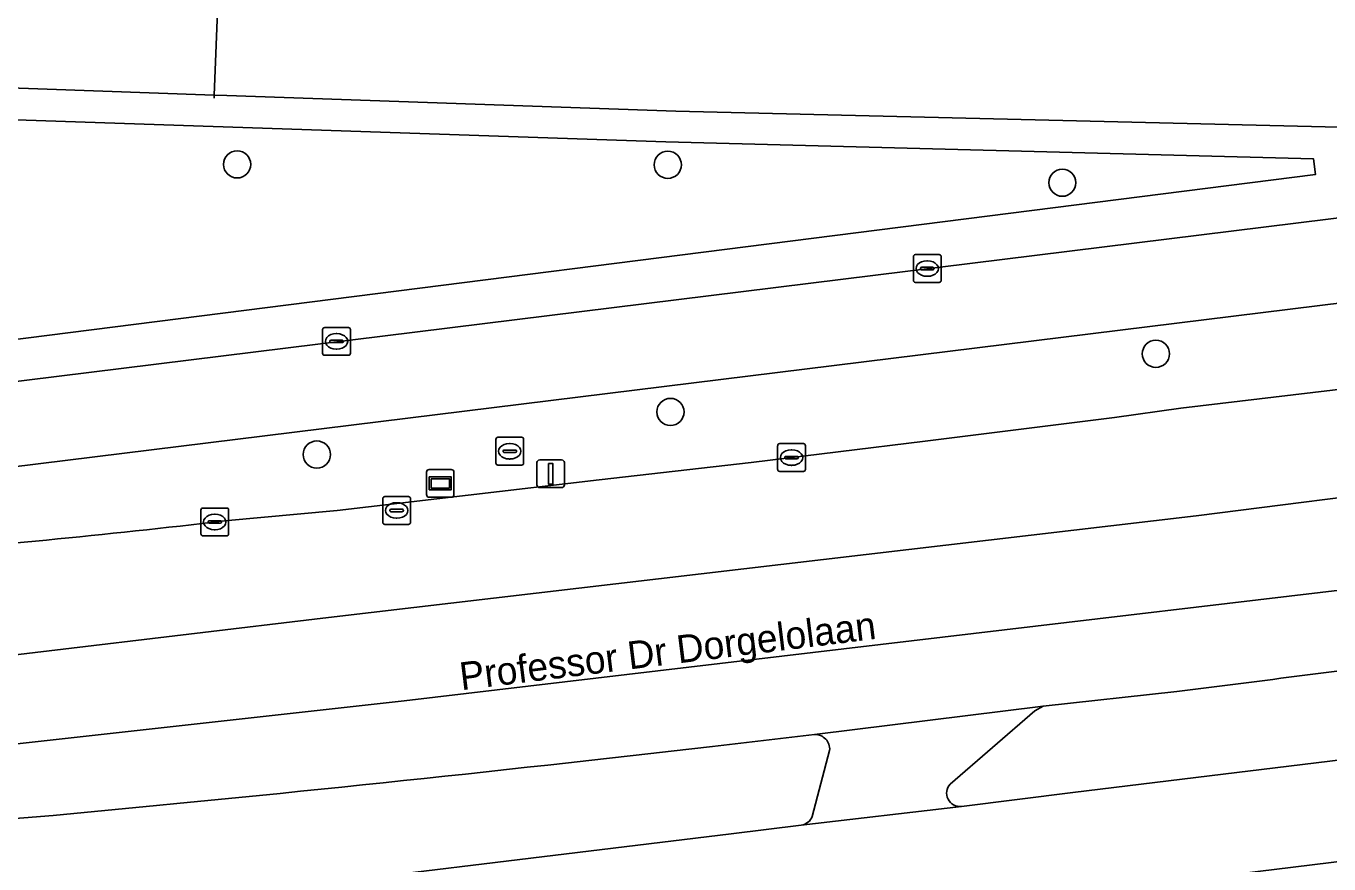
# Model space of a CAD drawing. Extents: x 161477 to 163040, y 383680 to 384871.
# Drawn here: x 161710.95 to 161757.86, y 384006.51 to 384036.66 of the extents above; entities that cross this region are included whole.
import ezdxf

# ---------------------------------------------------------------- set-up
doc = ezdxf.new("R2010")
doc.units = 0
for name, color, linetype in [('IMGEO_Berm_groen', 7, 'Continuous'), ('IMGEO_Boom', 7, 'Continuous'), ('IMGEO_Fietspad_gesloten', 7, 'Continuous'), ('IMGEO_Fietspad_open', 7, 'Continuous'), ('IMGEO_Kolk', 7, 'Continuous'), ('IMGEO_Lichtmast', 7, 'Continuous'), ('IMGEO_Lijnafwatering', 7, 'Continuous'), ('IMGEO_Openbare_ruimte_label', 7, 'Continuous'), ('IMGEO_Rijbaan_lokaal_gesloten', 7, 'Continuous'), ('IMGEO_Rioolput', 7, 'Continuous'), ('IMGEO_Verklikker', 7, 'Continuous'), ('IMGEO_Voetpad_gesloten', 7, 'Continuous'), ('IMGEO_Voetpad_open', 7, 'Continuous')]:
    doc.layers.add(name, color=color, linetype=linetype)

msp = doc.modelspace()

# ---------------------------------------------------------------- linework, layer by layer
at = {"layer": 'IMGEO_Berm_groen'}
for points in [[(161718.096, 384018.853), (161722.153, 384019.231), (161731.582, 384020.326), (161737.062, 384020.952), (161743.325, 384021.716), (161750.139, 384022.575), (161752.521, 384022.902), (161758.694, 384023.638), (161765.407, 384024.434), (161773.852, 384025.569), (161780.934, 384026.394), (161789.811, 384027.457), (161796.662, 384028.308), (161802.176, 384029.078), (161803.723, 384029.183), (161808.93, 384029.766), (161813.278, 384030.282), (161823.202, 384031.479), (161830.293, 384032.344), (161838.36, 384033.362), (161846.778, 384034.306), (161857.408, 384035.62), (161864.1, 384036.367)], [(161757.379, 384031.316), (161757.305, 384031.876), (161733.987, 384032.488), (161701.381, 384033.589), (161700.35, 384033.55), (161699.371, 384033.385)], [(161693.867, 384029.204), (161693.407, 384028.292), (161693.069, 384027.332), (161692.822, 384026.215), (161693.842, 384025.924), (161693.834, 384026.258), (161702.945, 384026.672), (161702.989, 384026.278), (161703.08, 384024.434), (161757.379, 384031.316)], [(161763.653, 384027.361), (161706.222, 384020.27), (161703.259, 384019.694)], [(161744.626, 384008.574), (161748.637, 384009.081), (161823.343, 384018.177), (161854.166, 384022.062), (161862.148, 384023.025)], [(161752.379, 384012.714), (161747.565, 384012.187), (161747.265, 384012.019), (161744.223, 384009.381)], [(161739.341, 384011.163), (161735.662, 384010.732)], [(161739.256, 384008.22), (161739.881, 384010.593)], [(161711.93, 384008.251), (161698.187, 384007.159), (161695.907, 384007), (161695.634, 384006.981), (161696.191, 384002.723), (161696.412, 384002.75), (161736.335, 384007.586), (161738.86, 384007.907)]]:
    msp.add_lwpolyline(points, dxfattribs=at)
for centre, radius, start, end in [((161683.186, 384312.146), 295.363, 274.28671, 276.78778), ((161586.568, 385343.237), 1340.815, 277.10362, 277.501004), ((161739.357, 384010.638), 0.526, 355.1239, 91.7798), ((161606.132, 385135.008), 1131.713, 275.364128, 276.572189), ((161744.576, 384009.053), 0.482, 137.1227, 275.9506), ((161738.801, 384008.388), 0.485, 276.9717, 339.6743)]:
    msp.add_arc(centre, radius, start, end, dxfattribs=at)
at = {"layer": 'IMGEO_Boom'}
for centre in [(161718.548, 384031.679), (161734.053, 384031.665), (161748.259, 384031.02), (161751.627, 384024.864), (161734.149, 384022.771), (161721.419, 384021.238)]:
    msp.add_circle(centre, 0.489, dxfattribs=at)
at = {"layer": 'IMGEO_Fietspad_gesloten'}
msp.add_lwpolyline([(161700.668, 384034.787), (161717.726, 384034.171), (161718.177, 384034.155), (161734.34, 384033.599), (161758.72, 384033.003), (161764.181, 384032.902)], dxfattribs=at)
at = {"layer": 'IMGEO_Fietspad_open'}
for points in [[(161763.653, 384027.361), (161763.253, 384030.692), (161762.659, 384030.32), (161759.087, 384029.863), (161705.045, 384023.188), (161702.143, 384022.584), (161699.157, 384022.191), (161694.128, 384021.966), (161693.678, 384021.946), (161694.02, 384019.337), (161694.073, 384018.934), (161694.486, 384018.953), (161695.454, 384018.996), (161699.282, 384019.167)], [(161703.259, 384019.694), (161706.222, 384020.27), (161763.653, 384027.361)]]:
    msp.add_lwpolyline(points, dxfattribs=at)
at = {"layer": 'IMGEO_Kolk'}
for p, q in [((161742.896, 384027.506), (161742.896, 384028.358)), ((161742.971, 384028.432), (161743.823, 384028.432)), ((161743.384, 384028.212), (161743.409, 384028.212)), ((161743.897, 384028.358), (161743.897, 384027.506)), ((161743.155, 384027.926), (161743.155, 384027.938)), ((161743.593, 384027.889), (161743.195, 384027.889)), ((161743.198, 384027.975), (161743.596, 384027.975)), ((161743.407, 384027.652), (161743.382, 384027.652)), ((161743.639, 384027.938), (161743.639, 384027.926)), ((161743.823, 384027.432), (161742.971, 384027.432)), ((161721.628, 384024.883), (161721.628, 384025.735)), ((161721.703, 384025.809), (161722.555, 384025.809)), ((161722.629, 384025.735), (161722.629, 384024.883)), ((161721.887, 384025.303), (161721.887, 384025.315)), ((161722.325, 384025.266), (161721.927, 384025.266)), ((161721.93, 384025.352), (161722.328, 384025.352)), ((161722.116, 384025.589), (161722.141, 384025.589)), ((161722.371, 384025.315), (161722.371, 384025.303)), ((161722.555, 384024.809), (161721.703, 384024.809)), ((161722.139, 384025.029), (161722.114, 384025.029)), ((161738.01, 384020.704), (161738.01, 384021.556)), ((161738.085, 384021.63), (161738.937, 384021.63)), ((161739.011, 384021.556), (161739.011, 384020.704)), ((161738.269, 384021.124), (161738.269, 384021.136)), ((161738.707, 384021.087), (161738.309, 384021.087)), ((161738.312, 384021.173), (161738.71, 384021.173)), ((161738.498, 384021.41), (161738.523, 384021.41)), ((161738.753, 384021.136), (161738.753, 384021.124)), ((161738.937, 384020.63), (161738.085, 384020.63)), ((161738.521, 384020.85), (161738.496, 384020.85)), ((161723.792, 384018.8), (161723.792, 384019.652)), ((161723.867, 384019.726), (161724.719, 384019.726)), ((161724.793, 384019.652), (161724.793, 384018.8)), ((161717.242, 384018.387), (161717.242, 384019.239)), ((161717.317, 384019.313), (161718.169, 384019.313)), ((161718.243, 384019.239), (161718.243, 384018.387)), ((161724.051, 384019.22), (161724.051, 384019.232)), ((161724.489, 384019.183), (161724.091, 384019.183)), ((161724.094, 384019.269), (161724.492, 384019.269)), ((161724.28, 384019.506), (161724.305, 384019.506)), ((161724.535, 384019.232), (161724.535, 384019.22)), ((161717.501, 384018.807), (161717.501, 384018.819)), ((161717.939, 384018.77), (161717.541, 384018.77)), ((161717.544, 384018.856), (161717.942, 384018.856)), ((161717.73, 384019.093), (161717.755, 384019.093)), ((161717.985, 384018.819), (161717.985, 384018.807)), ((161724.719, 384018.726), (161723.867, 384018.726)), ((161724.303, 384018.946), (161724.278, 384018.946)), ((161718.169, 384018.313), (161717.317, 384018.313)), ((161717.753, 384018.533), (161717.728, 384018.533))]:
    msp.add_line(p, q, dxfattribs=at)
for points in [[(161742.896, 384027.506), (161742.896, 384028.358)], [(161742.971, 384028.432), (161743.823, 384028.432)], [(161743.897, 384028.358), (161743.897, 384027.506)], [(161743.823, 384027.432), (161742.971, 384027.432)], [(161721.628, 384024.883), (161721.628, 384025.735)], [(161721.703, 384025.809), (161722.555, 384025.809)], [(161722.629, 384025.735), (161722.629, 384024.883)], [(161722.555, 384024.809), (161721.703, 384024.809)], [(161738.01, 384020.704), (161738.01, 384021.556)], [(161738.085, 384021.63), (161738.937, 384021.63)], [(161739.011, 384021.556), (161739.011, 384020.704)], [(161738.937, 384020.63), (161738.085, 384020.63)], [(161723.792, 384018.8), (161723.792, 384019.652)], [(161723.867, 384019.726), (161724.719, 384019.726)], [(161724.793, 384019.652), (161724.793, 384018.8)], [(161717.242, 384018.387), (161717.242, 384019.239)], [(161717.317, 384019.313), (161718.169, 384019.313)], [(161718.243, 384019.239), (161718.243, 384018.387)], [(161724.719, 384018.726), (161723.867, 384018.726)], [(161718.169, 384018.313), (161717.317, 384018.313)]]:
    msp.add_lwpolyline(points, dxfattribs=at)
for centre, radius, start, end in [((161742.973, 384028.356), 0.0765, 91.552, 178.448), ((161742.973, 384028.356), 0.0765, 91.552, 178.448), ((161743.821, 384028.356), 0.0765, 1.552, 88.448), ((161743.821, 384028.356), 0.0765, 1.552, 88.448), ((161743.195, 384027.935), 0.0403, 85.8775, 175.7526), ((161743.192, 384027.925), 0.0366, 178.938, 274.7102), ((161743.596, 384027.932), 0.043, 264.8664, 352.4533), ((161743.6, 384027.937), 0.0386, 1.7309, 96.639), ((161742.973, 384027.508), 0.0765, 181.552, 268.448), ((161742.973, 384027.508), 0.0765, 181.552, 268.448), ((161743.821, 384027.508), 0.0765, 271.552, 358.448), ((161743.821, 384027.508), 0.0765, 271.552, 358.448), ((161721.705, 384025.733), 0.0765, 91.552, 178.448), ((161721.705, 384025.733), 0.0765, 91.552, 178.448), ((161722.553, 384025.733), 0.0765, 1.552, 88.448), ((161722.553, 384025.733), 0.0765, 1.552, 88.448), ((161721.927, 384025.312), 0.0403, 85.8775, 175.7526), ((161721.924, 384025.302), 0.0366, 178.938, 274.7102), ((161722.328, 384025.309), 0.043, 264.8664, 352.4533), ((161722.332, 384025.314), 0.0386, 1.7309, 96.639), ((161721.705, 384024.885), 0.0765, 181.552, 268.448), ((161721.705, 384024.885), 0.0765, 181.552, 268.448), ((161722.553, 384024.885), 0.0765, 271.552, 358.448), ((161722.553, 384024.885), 0.0765, 271.552, 358.448), ((161738.087, 384021.554), 0.0765, 91.552, 178.448), ((161738.087, 384021.554), 0.0765, 91.552, 178.448), ((161738.935, 384021.554), 0.0765, 1.552, 88.448), ((161738.935, 384021.554), 0.0765, 1.552, 88.448), ((161738.309, 384021.133), 0.0403, 85.8775, 175.7526), ((161738.306, 384021.123), 0.0366, 178.938, 274.7102), ((161738.71, 384021.13), 0.043, 264.8664, 352.4533), ((161738.714, 384021.135), 0.0386, 1.7309, 96.639), ((161738.087, 384020.706), 0.0765, 181.552, 268.448), ((161738.087, 384020.706), 0.0765, 181.552, 268.448), ((161738.935, 384020.706), 0.0765, 271.552, 358.448), ((161738.935, 384020.706), 0.0765, 271.552, 358.448), ((161723.869, 384019.65), 0.0765, 91.552, 178.448), ((161723.869, 384019.65), 0.0765, 91.552, 178.448), ((161724.717, 384019.65), 0.0765, 1.552, 88.448), ((161724.717, 384019.65), 0.0765, 1.552, 88.448), ((161717.319, 384019.237), 0.0765, 91.552, 178.448), ((161717.319, 384019.237), 0.0765, 91.552, 178.448), ((161718.167, 384019.237), 0.0765, 1.552, 88.448), ((161718.167, 384019.237), 0.0765, 1.552, 88.448), ((161724.091, 384019.229), 0.0403, 85.8775, 175.7526), ((161724.088, 384019.219), 0.0366, 178.938, 274.7102), ((161724.492, 384019.226), 0.043, 264.8664, 352.4533), ((161724.496, 384019.231), 0.0386, 1.7309, 96.639), ((161717.541, 384018.816), 0.0403, 85.8775, 175.7526), ((161717.538, 384018.806), 0.0366, 178.938, 274.7102), ((161717.942, 384018.813), 0.043, 264.8664, 352.4533), ((161717.946, 384018.818), 0.0386, 1.7309, 96.639), ((161723.869, 384018.802), 0.0765, 181.552, 268.448), ((161723.869, 384018.802), 0.0765, 181.552, 268.448), ((161724.717, 384018.802), 0.0765, 271.552, 358.448), ((161724.717, 384018.802), 0.0765, 271.552, 358.448), ((161717.319, 384018.389), 0.0765, 181.552, 268.448), ((161717.319, 384018.389), 0.0765, 181.552, 268.448), ((161718.167, 384018.389), 0.0765, 271.552, 358.448), ((161718.167, 384018.389), 0.0765, 271.552, 358.448)]:
    msp.add_arc(centre, radius, start, end, dxfattribs=at)
for centre, major_axis, ratio, start_param, end_param in [((161743.383, 384027.932), (-0.387, 0.002), 0.722429, 4.712389, 7.853982), ((161743.408, 384027.932), (-0.39, 0.002), 0.717154, 1.570796, 4.712389), ((161722.115, 384025.309), (-0.387, 0.002), 0.722429, 4.712389, 7.853982), ((161722.14, 384025.309), (-0.39, 0.002), 0.717154, 1.570796, 4.712389), ((161738.497, 384021.13), (-0.387, 0.002), 0.722429, 4.712389, 7.853982), ((161738.522, 384021.13), (-0.39, 0.002), 0.717154, 1.570796, 4.712389), ((161724.279, 384019.226), (-0.387, 0.002), 0.722429, 4.712389, 7.853982), ((161724.304, 384019.226), (-0.39, 0.002), 0.717154, 1.570796, 4.712389), ((161717.729, 384018.813), (-0.387, 0.002), 0.722429, 4.712389, 7.853982), ((161717.754, 384018.813), (-0.39, 0.002), 0.717154, 1.570796, 4.712389)]:
    msp.add_ellipse(centre, major_axis=major_axis, ratio=ratio, start_param=start_param, end_param=end_param, dxfattribs=at)
at = {"layer": 'IMGEO_Lichtmast'}
for p, q in [((161729.443, 384021.047), (161730.233, 384021.047)), ((161730.233, 384021.047), (161729.443, 384021.047)), ((161729.343, 384020.147), (161729.343, 384020.947)), ((161729.343, 384020.947), (161729.343, 384020.147)), ((161730.333, 384020.947), (161730.333, 384020.147)), ((161730.333, 384020.147), (161730.333, 384020.947)), ((161730.233, 384020.047), (161729.443, 384020.047)), ((161729.443, 384020.047), (161730.233, 384020.047))]:
    msp.add_line(p, q, dxfattribs=at)
msp.add_lwpolyline([(161729.763, 384020.922), (161729.913, 384020.922), (161729.913, 384020.172), (161729.763, 384020.172), (161729.763, 384020.922)], dxfattribs=at)
for centre, start, end in [((161729.443, 384020.947), 90, 180), ((161729.443, 384020.947), 90, 180), ((161730.233, 384020.947), 0, 90), ((161730.233, 384020.947), 360, 90), ((161729.443, 384020.147), 180, 270), ((161729.443, 384020.147), 180, 270), ((161730.233, 384020.147), 270, 0), ((161730.233, 384020.147), 270, 0)]:
    msp.add_arc(centre, 0.1, start, end, dxfattribs=at)
at = {"layer": 'IMGEO_Lijnafwatering'}
msp.add_lwpolyline([(161717.723, 384034.066), (161717.726, 384034.171), (161717.868, 384037.79), (161717.906, 384038.868)], dxfattribs=at)
at = {"layer": 'IMGEO_Rijbaan_lokaal_gesloten'}
for points in [[(161705.264, 384017.609), (161695.591, 384016.774), (161695.172, 384016.745), (161694.752, 384016.717), (161694.365, 384016.691), (161694.855, 384012.926), (161696.893, 384013.027), (161706.74, 384013.577), (161721.837, 384015.377), (161753.08, 384019.028), (161795.621, 384024.429), (161827.864, 384028.429), (161871.905, 384033.68), (161895.749, 384036.581), (161917.195, 384039.231), (161945.288, 384042.532), (161960.735, 384044.482), (161993.828, 384048.483), (162005.138, 384049.833), (162024.421, 384052.135)], [(161864.1, 384036.367), (161857.408, 384035.62), (161846.778, 384034.306), (161838.36, 384033.362), (161830.293, 384032.344), (161823.202, 384031.479), (161813.278, 384030.282), (161808.93, 384029.766), (161803.723, 384029.183), (161802.176, 384029.078), (161796.662, 384028.308), (161789.811, 384027.457), (161780.934, 384026.394), (161773.852, 384025.569), (161765.407, 384024.434), (161758.694, 384023.638), (161752.521, 384022.902), (161750.139, 384022.575), (161743.325, 384021.716), (161737.062, 384020.952), (161731.582, 384020.326), (161722.153, 384019.231), (161718.096, 384018.853)], [(161871.905, 384033.68), (161827.864, 384028.429), (161795.621, 384024.429), (161753.08, 384019.028), (161721.837, 384015.377), (161706.74, 384013.577), (161696.893, 384013.027), (161694.855, 384012.926), (161695.269, 384009.746), (161701.12, 384010.023), (161710.519, 384010.823), (161724.566, 384012.374), (161779.16, 384018.826), (161800.208, 384021.201), (161822.654, 384023.966), (161852.473, 384027.711), (161858.477, 384028.412), (161863.792, 384029.049)], [(161862.148, 384023.025), (161854.166, 384022.062), (161823.343, 384018.177), (161748.637, 384009.081), (161744.626, 384008.574), (161738.86, 384007.907), (161736.335, 384007.586), (161696.412, 384002.75), (161696.191, 384002.723), (161696.51, 384000), (161696.618, 383999.076), (161717.081, 384001.544), (161768.879, 384007.897), (161825.477, 384014.75), (161917.35, 384025.954)], [(161917.35, 384025.954), (161825.477, 384014.75), (161768.879, 384007.897), (161717.081, 384001.544), (161696.618, 383999.076), (161697.015, 383995.692), (161711.954, 383997.541), (161763.35, 384003.723), (161772.777, 384004.866), (161779.357, 384005.838), (161786.031, 384006.552), (161787.004, 384006.583), (161794.62, 384007.571), (161802.199, 384008.506), (161811.276, 384009.575), (161828.807, 384011.75), (161835.35, 384012.513), (161842.62, 384013.413), (161849.74, 384014.259), (161850.706, 384014.47), (161854.527, 384014.894), (161865.049, 384016.046)], [(161789.224, 384017.828), (161800.208, 384021.201), (161779.16, 384018.826), (161724.566, 384012.374), (161710.519, 384010.823), (161701.12, 384010.023), (161695.269, 384009.746), (161695.634, 384006.981), (161695.907, 384007), (161698.187, 384007.159), (161711.93, 384008.251)], [(161735.662, 384010.732), (161739.341, 384011.163), (161747.565, 384012.187), (161752.379, 384012.714)]]:
    msp.add_lwpolyline(points, dxfattribs=at)
for centre, radius, start, end in [((161683.186, 384312.146), 295.363, 274.28671, 276.78778), ((161586.568, 385343.237), 1340.815, 277.10362, 277.501004), ((161606.132, 385135.008), 1131.713, 275.364128, 276.572189)]:
    msp.add_arc(centre, radius, start, end, dxfattribs=at)
at = {"layer": 'IMGEO_Rioolput'}
for p, q in [((161727.863, 384020.932), (161727.863, 384021.784)), ((161727.938, 384021.858), (161728.79, 384021.858)), ((161728.351, 384021.638), (161728.376, 384021.638)), ((161728.864, 384021.784), (161728.864, 384020.932)), ((161728.122, 384021.352), (161728.122, 384021.364)), ((161728.56, 384021.315), (161728.162, 384021.315)), ((161728.165, 384021.401), (161728.563, 384021.401)), ((161728.374, 384021.078), (161728.349, 384021.078)), ((161728.606, 384021.364), (161728.606, 384021.352)), ((161728.79, 384020.858), (161727.938, 384020.858))]:
    msp.add_line(p, q, dxfattribs=at)
for points in [[(161727.863, 384020.932), (161727.863, 384021.784)], [(161727.938, 384021.858), (161728.79, 384021.858)], [(161728.864, 384021.784), (161728.864, 384020.932)], [(161728.79, 384020.858), (161727.938, 384020.858)]]:
    msp.add_lwpolyline(points, dxfattribs=at)
for centre, radius, start, end in [((161727.94, 384021.782), 0.0765, 91.552, 178.448), ((161727.94, 384021.782), 0.0765, 91.552, 178.448), ((161728.788, 384021.782), 0.0765, 1.552, 88.448), ((161728.788, 384021.782), 0.0765, 1.552, 88.448), ((161728.162, 384021.361), 0.0403, 85.8775, 175.7526), ((161728.159, 384021.351), 0.0366, 178.938, 274.7102), ((161728.563, 384021.358), 0.043, 264.8664, 352.4533), ((161728.567, 384021.363), 0.0386, 1.7309, 96.639), ((161727.94, 384020.934), 0.0765, 181.552, 268.448), ((161727.94, 384020.934), 0.0765, 181.552, 268.448), ((161728.788, 384020.934), 0.0765, 271.552, 358.448), ((161728.788, 384020.934), 0.0765, 271.552, 358.448)]:
    msp.add_arc(centre, radius, start, end, dxfattribs=at)
for centre, major_axis, ratio, start_param, end_param in [((161728.35, 384021.358), (-0.387, 0.002), 0.722429, 4.712389, 7.853982), ((161728.375, 384021.358), (-0.39, 0.002), 0.717154, 1.570796, 4.712389)]:
    msp.add_ellipse(centre, major_axis=major_axis, ratio=ratio, start_param=start_param, end_param=end_param, dxfattribs=at)
at = {"layer": 'IMGEO_Verklikker'}
for p, q in [((161725.367, 384019.801), (161725.367, 384020.601)), ((161725.367, 384020.601), (161725.367, 384019.801)), ((161725.467, 384020.701), (161726.257, 384020.701)), ((161726.257, 384020.701), (161725.467, 384020.701)), ((161726.357, 384020.601), (161726.357, 384019.801)), ((161726.357, 384019.801), (161726.357, 384020.601)), ((161726.257, 384019.701), (161725.467, 384019.701)), ((161725.467, 384019.701), (161726.257, 384019.701))]:
    msp.add_line(p, q, dxfattribs=at)
for points in [[(161725.468, 384020.433), (161726.256, 384020.433), (161726.256, 384019.969), (161725.468, 384019.969), (161725.468, 384020.433)], [(161725.533, 384020.368), (161725.533, 384020.034), (161726.191, 384020.034), (161726.191, 384020.368), (161725.533, 384020.368)]]:
    msp.add_lwpolyline(points, dxfattribs=at)
for centre, start, end in [((161725.467, 384020.601), 90, 180), ((161725.467, 384020.601), 90, 180), ((161726.257, 384020.601), 0, 90), ((161726.257, 384020.601), 360, 90), ((161725.467, 384019.801), 180, 270), ((161725.467, 384019.801), 180, 270), ((161726.257, 384019.801), 270, 0), ((161726.257, 384019.801), 270, 0)]:
    msp.add_arc(centre, 0.1, start, end, dxfattribs=at)
at = {"layer": 'IMGEO_Voetpad_gesloten'}
for points in [[(161744.223, 384009.381), (161747.265, 384012.019), (161747.565, 384012.187), (161739.341, 384011.163)], [(161739.881, 384010.593), (161739.256, 384008.22)], [(161738.86, 384007.907), (161744.626, 384008.574)]]:
    msp.add_lwpolyline(points, dxfattribs=at)
for centre, radius, start, end in [((161739.357, 384010.638), 0.526, 355.1239, 91.7798), ((161744.576, 384009.053), 0.482, 137.1227, 275.9506), ((161738.801, 384008.388), 0.485, 276.9717, 339.6743)]:
    msp.add_arc(centre, radius, start, end, dxfattribs=at)
at = {"layer": 'IMGEO_Voetpad_open'}
msp.add_lwpolyline([(161758.72, 384033.003), (161734.34, 384033.599), (161718.177, 384034.155), (161717.726, 384034.171), (161700.668, 384034.787), (161701.381, 384033.589), (161733.987, 384032.488), (161757.305, 384031.876), (161757.379, 384031.316), (161703.08, 384024.434), (161702.989, 384026.278), (161700.729, 384026.171), (161700.797, 384024.245), (161701.095, 384024.258), (161701.166, 384023.924), (161693.934, 384023.598), (161693.465, 384023.577), (161693.579, 384022.704), (161693.678, 384021.946), (161694.128, 384021.966), (161699.157, 384022.191), (161702.143, 384022.584), (161705.045, 384023.188), (161759.087, 384029.863)], close=True, dxfattribs=at)

# ---------------------------------------------------------------- texts
at = {"layer": 'IMGEO_Openbare_ruimte_label'}
msp.add_text('Professor Dr Dorgelolaan', height=1, rotation=7.0681, dxfattribs=at).set_placement((161726.622, 384012.754))

doc.saveas('drawing.dxf')
